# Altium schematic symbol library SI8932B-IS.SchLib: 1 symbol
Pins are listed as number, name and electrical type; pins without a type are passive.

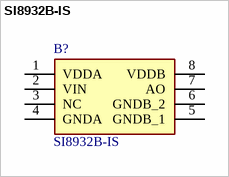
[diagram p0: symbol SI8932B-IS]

## SI8932B-IS
designator B?
Isolation Amplifiers Isolated voltage sensor with single ended input and single ended output. Narrow body S08.; Manufacturer_Name: Skyworks; Geometry.Height: 1.75mm
footprint SOIC127P600X175-8N
pins: 1 VDDA, 2 VIN, 3 NC, 4 GNDA, 5 GNDB_1, 6 GNDB_2, 7 AO, 8 VDDB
